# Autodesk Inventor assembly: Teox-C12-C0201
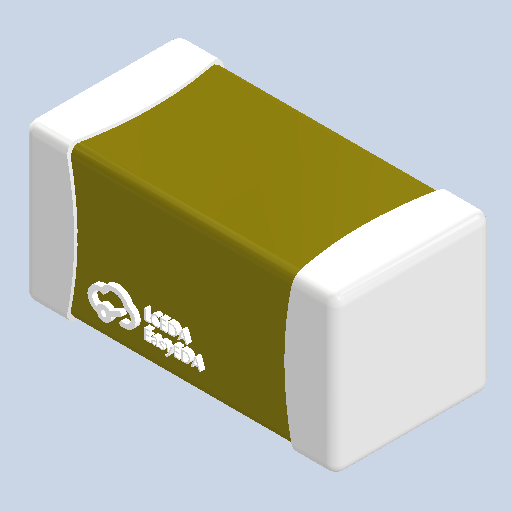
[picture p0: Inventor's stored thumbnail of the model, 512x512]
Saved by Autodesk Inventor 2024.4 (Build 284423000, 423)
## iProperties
Created: 2025-05
Part Number: Teox-C12-C0201
Document SubType Name: Assembly
Designer: AdminForWorker
Title: Teox-C12-C0201
Author: AdminForWorker
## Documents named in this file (2)
- c:\worker\convert-fusion-r02-cosv3\tmp\job-1\2\temp\files\be827049-a7f2-47ea-a815-8d9efd6bfce9\Teox-C12-C0201.iam
- c:\worker\convert-fusion-r02-cosv3\tmp\job-1\2\temp\files\be827049-a7f2-47ea-a815-8d9efd6bfce9\COMPOUND (3).ipt
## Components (1 placed, 1 different names)
1. COMPOUND (3):1
